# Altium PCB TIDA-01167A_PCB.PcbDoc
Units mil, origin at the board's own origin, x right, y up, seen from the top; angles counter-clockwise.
Board outline 1968.5 x 1574.8 mil, 2 copper layers (Top Layer, Bottom Layer), stack 62 mil thick; 65 components, 25 nets, 160 pads, 86 vias.
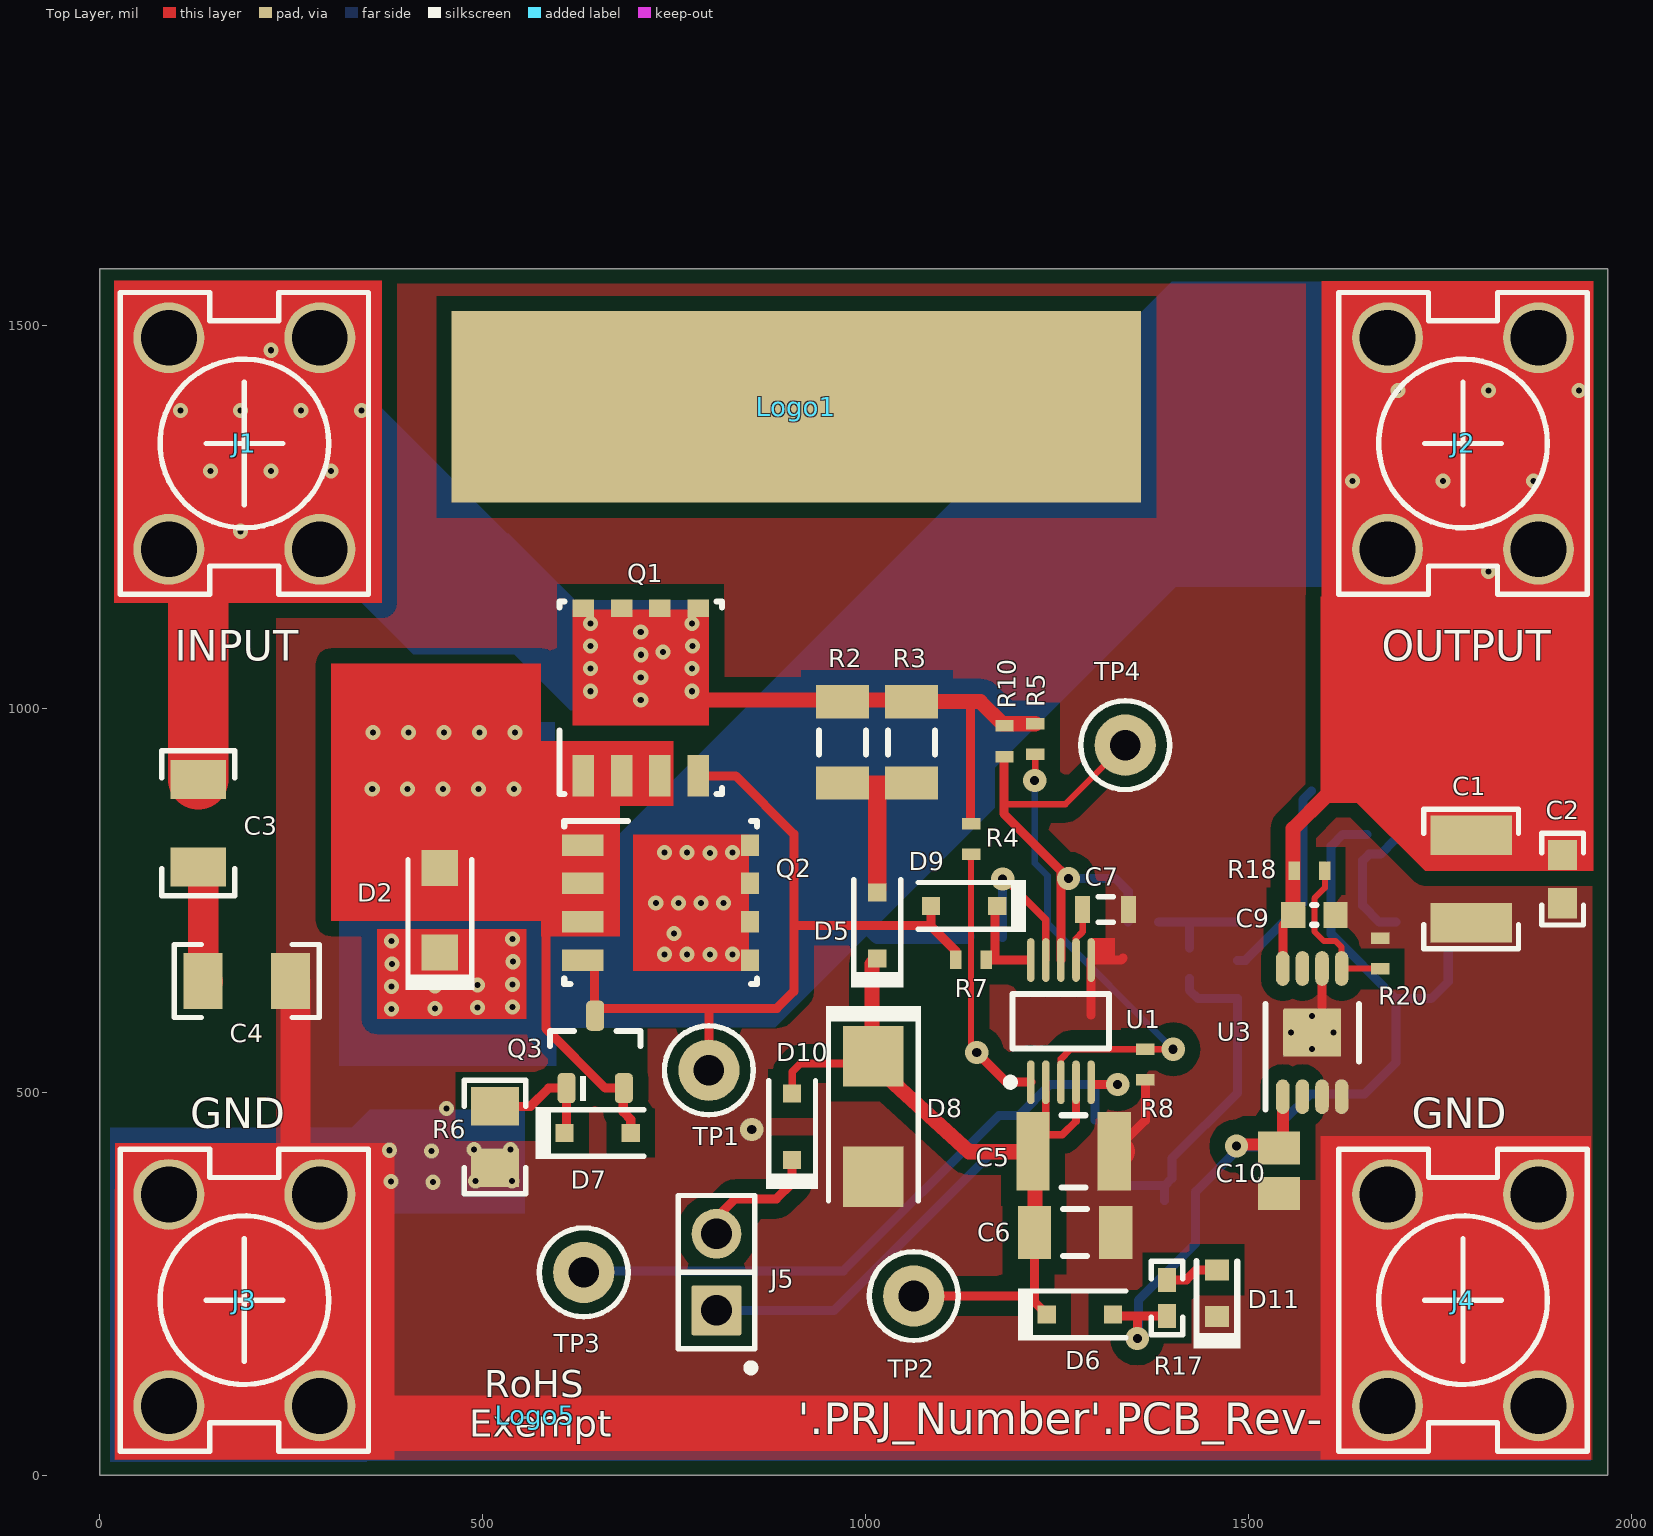
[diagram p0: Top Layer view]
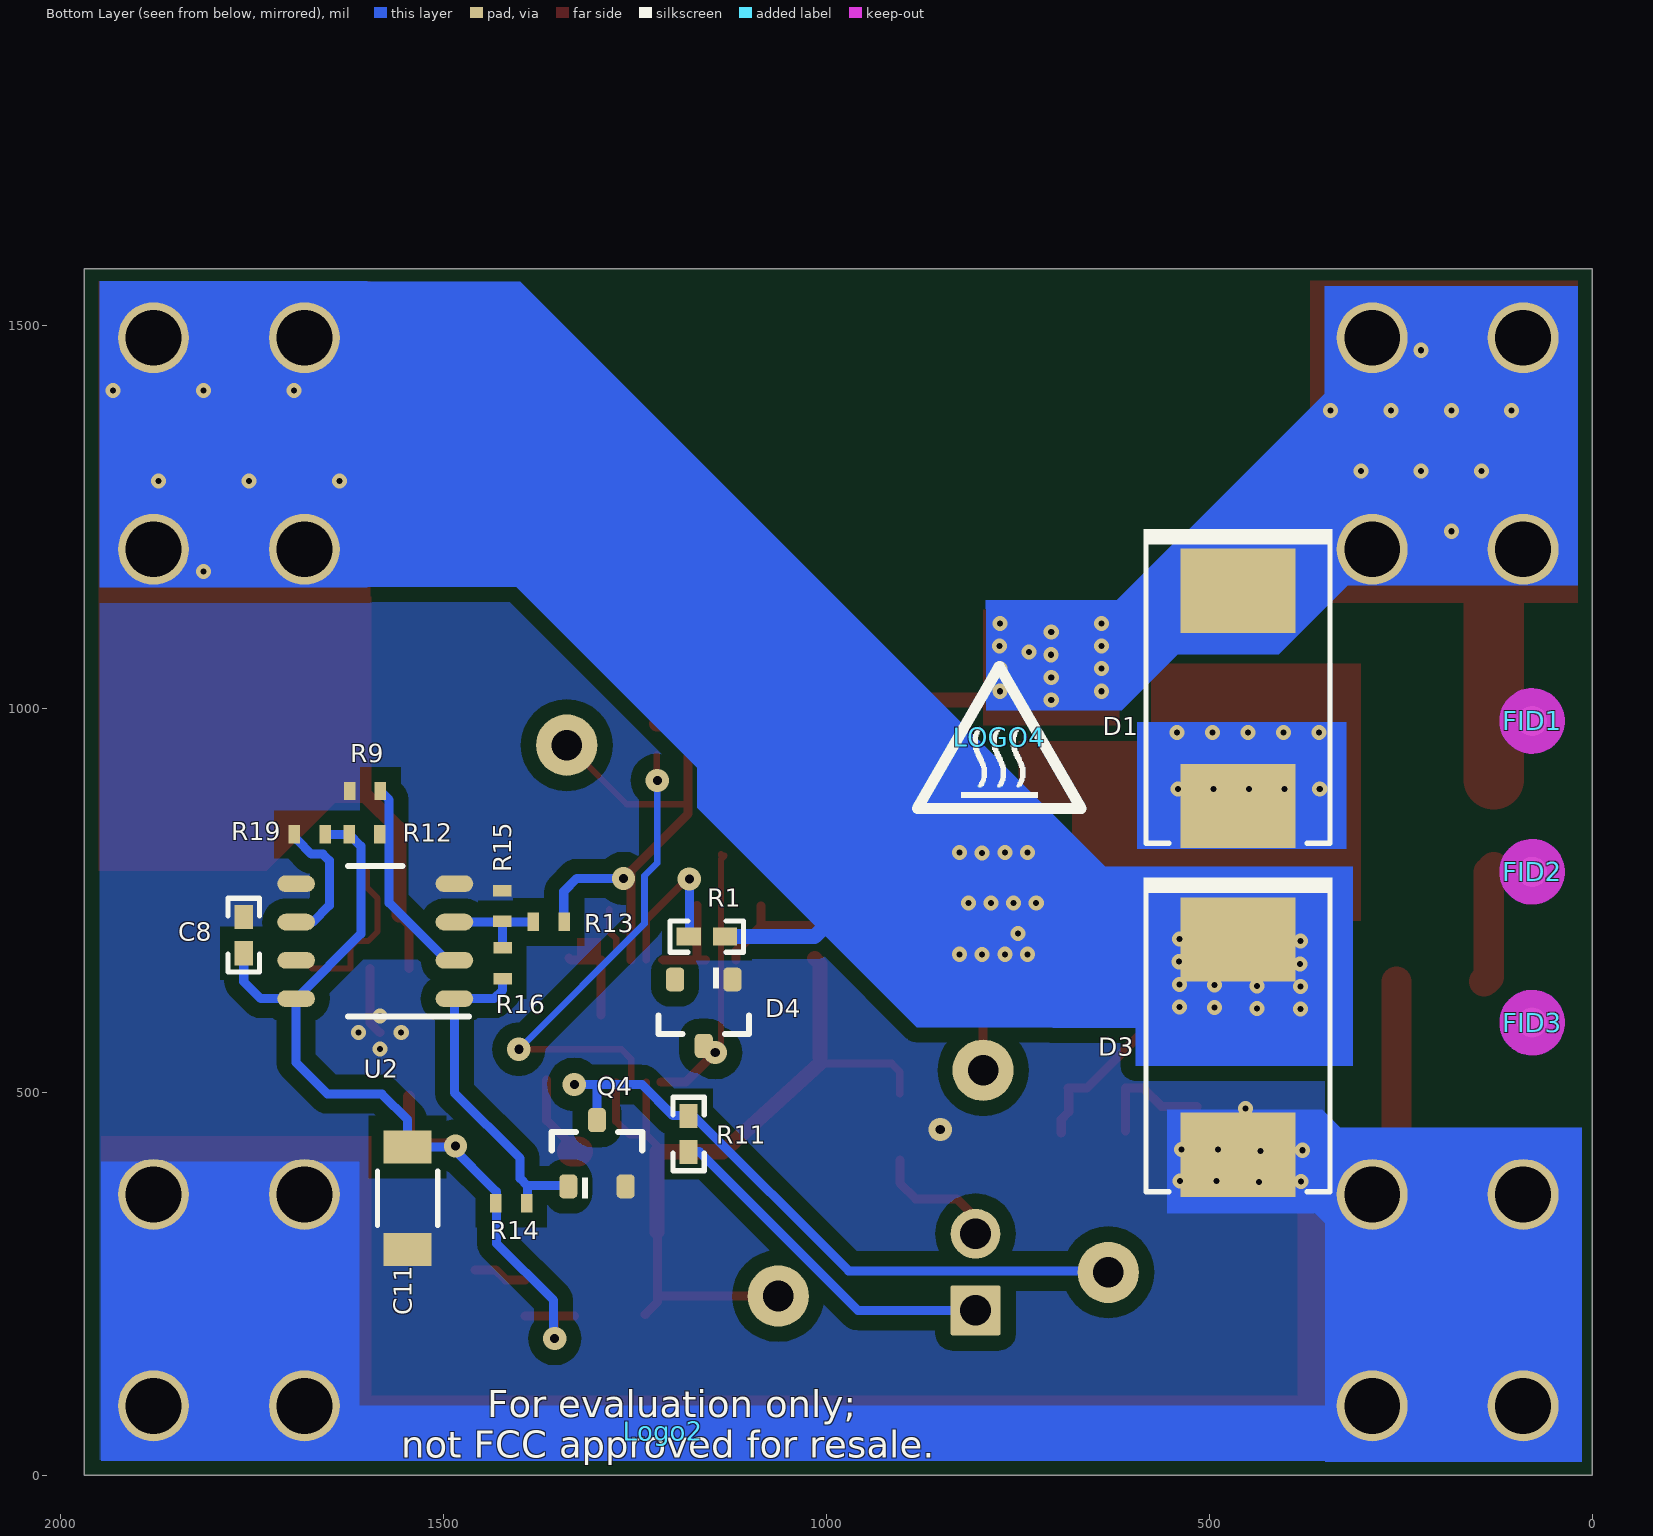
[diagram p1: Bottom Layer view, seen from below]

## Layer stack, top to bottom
Top Solder: solder mask 0.4, Solder Resist, Dk 3.5
Top Layer: signal copper 1.4
Dielectric1: core 59.2, FR-4, Dk 4.8
Bottom Layer: signal copper 1.4
Bottom Solder: solder mask 0.4, Solder Resist, Dk 3.5

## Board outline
0,0 1968.5,0 1968.5,1574.8 0,1574.8

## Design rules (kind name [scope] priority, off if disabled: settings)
AcuteAngle [All] p1: minimum=4.50000000000000E+0001 checktracksonly=FALSE
AssemblyTestPointUsage [All] p1: valid=2
BoardOutlineClearance BoardOutlineClearance_MountingHoles [OnCopper and InComponentClass('Mounting Holes')] p1: gap=19.68
BoardOutlineClearance BoardOutlineClearance_Poly [OnCopper and InPoly] p2: gap=19.68
BoardOutlineClearance [OnCopper and Not InComponentClass('Logo') and not InComponentClass('FiducialMark') and not InRegion(1000,500,4000,800)] p3: gap=0 except(19.68: Poly-OutlineEdge)
Clearance Clearance_1 [InNamedPolygon('BOTTOM_LAYER_GND_P000')] p1: gap=10
Clearance Clearance_Keepouts [((IsTrack Or IsArc) And Not InPoly) And IsFree and IsKeepOut vs ((IsTrack Or IsArc) And Not InPoly) And IsFree and IsKeepOut] p2: gap=15.75
Clearance Clearance_Poly [InPolygon] p3: gap=19.68
Clearance [All] p4: gap=7.87
ComponentClearance ComponentClearance_MountingHoles_FiducialMarks [InComponentClass('Mounting Holes') vs InComponentClass('FiducialMark')] p1: gap=50 collisioncheckmode=3 verticalgap=10 showdistances=FALSE
ComponentClearance ComponentClearance_Shunt [InComponentClass('Header') vs InComponentClass('Shunt')] p2: gap=0 collisioncheckmode=3 verticalgap=0 showdistances=FALSE
ComponentClearance ComponentClearance_Logo [InComponentClass('Logo')] p3: gap=50 collisioncheckmode=3 verticalgap=10 showdistances=FALSE
ComponentClearance ComponentClearance_ScrewToNut [(HasFootprint('NY PMS 440 0025 PH')) vs (HasFootprint('Keystone_1902C'))] p4: gap=5 collisioncheckmode=3 verticalgap=10 showdistances=FALSE
ComponentClearance ComponentClearance_MountingHoles [InComponentClass('Mounting Holes')] p5: gap=250 collisioncheckmode=3 verticalgap=100000 showdistances=FALSE
ComponentClearance ComponentClearance_SmallPassives [HasFootprint('0201*') or HasFootprint('0402*') or HasFootprint('0508') or HasFootprint('0603*') or HasFootprint('0612') or HasFootprint('0805*') or HasFootprint('0815*') or HasFootprint('0830*') or HasFootprint('1206*') or HasFootprint('1210*') or HasFootprint('1808*') or HasFootprint('1812*') or HasFootprint('1825*') or HasFootprint('2010*') or HasFootprint('2220*') or HasFootprint('2225*') or HasFootprint('2512*') or HasFootprint('2728*') or HasFootprint('3518*') vs HasFootprint('0201*') or HasFootprint('0402*') or HasFootprint('0508') or HasFootprint('0603*') or HasFootprint('0612') or HasFootprint('0805*') or HasFootprint('0815*') or HasFootprint('0830*') or HasFootprint('1206*') or HasFootprint('1210*') or HasFootprint('1808*') or HasFootprint('1812*') or HasFootprint('1825*') or HasFootprint('2010*') or HasFootprint('2220*') or HasFootprint('2225*') or HasFootprint('2512*') or HasFootprint('2728*') or HasFootprint('3518*')] p6: gap=14.96 collisioncheckmode=3 verticalgap=10 showdistances=FALSE
ComponentClearance ComponentClearance_THtoSMT [IsThruComponent vs IsSMTComponent] p7: gap=40 collisioncheckmode=3 verticalgap=30 showdistances=FALSE
ComponentClearance ComponentClearance_THtoTH [IsThruComponent vs IsThruComponent] p8: gap=30 collisioncheckmode=3 verticalgap=30 showdistances=FALSE
ComponentClearance [All] p9: gap=30 collisioncheckmode=3 verticalgap=3.94 showdistances=FALSE
DiffPairsRouting [All] p1: maxlimit=100 minlimit=10 mostfreqgap=10 toplayer_minwidth=15 toplayer_maxwidth=15 toplayer_prefwidth=15 bottomlayer_minwidth=15 bottomlayer_maxwidth=15 bottomlayer_prefwidth=15 maxuncoupledlength=1000
FabricationTestPointUsage TestPointUsage [All] p1: valid=2 allowmultiple=FALSE
FabricationTestpoint Testpoint [All] p1: side=3 testpointundercomponent=TRUE minsize=40 maxsize=100 preferedsize=60 minholesize=0 maxholesize=40 preferedholesize=32 testpointgrid=1 allowsidetop=TRUE allowsidebottom=TRUE usegrid=TRUE gridtolerance=0.01
FanoutControl Fanout_LCC [IsLCC] p1: bgadir=Out bgaviamode=Centered fanoutstyle=Auto fanoutdirection=Alternating viagrid=1 // Fanout_LCC (Default Rule)
FanoutControl Fanout_BGA [IsBGA] p2: bgadir=Out bgaviamode=Centered fanoutstyle=Auto fanoutdirection=Alternating viagrid=1 // Fanout_BGA (Default Rule)
FanoutControl Fanout_Default [All] p4: bgadir=Out bgaviamode=Centered fanoutstyle=Auto fanoutdirection=Alternating viagrid=1 // Fanout_Default (Default Rule)
FanoutControl Fanout_Small [(CompPinCount < 5)] p5: bgadir=Out bgaviamode=Centered fanoutstyle=Auto fanoutdirection=OutThenIn viagrid=1 // Fanout_Small (Default Rule)
HoleSize [All] p1: absolutevalues=TRUE maxlimit=251 minlimit=7.87 maxpercent=80.000 minpercent=20.000
MinimumAnnularRing MinimumAnnularRing_ThermalPadVias [IsVia and InAnyComponent] p1: minimumring=3.94
MinimumAnnularRing [All] p2: minimumring=5
MinimumSolderMaskSliver MinimumSolderMaskSliver_Logo [InComponentClass('Logo') vs InComponentClass('Logo')] p1: minsoldermaskwidth=0.7
MinimumSolderMaskSliver [All] p2: minsoldermaskwidth=4
PlaneConnect [All] p1: planeconnectstyle=Direct reliefexpansion=10 reliefentries=4 reliefconductorwidth=10 reliefairgap=10
PolygonConnect [All] p1: connectstyle=Direct reliefconductorwidth=10 reliefentries=4 polygonreliefangle="90 Angle" airgapwidth=10
RoutingVias ThermalPadVias [IsVia and InAnyComponent] p1: holewidth=7.87 width=19.68 viastyle="Through Hole" minholewidth=7.87 minwidth=19.68 maxholewidth=12.99 maxwidth=23.62
RoutingVias [All] p2: holewidth=16 width=34 viastyle="Through Hole" minholewidth=7.87 minwidth=19.68 maxholewidth=40 maxwidth=65
SilkToBoardRegionClearance [Not ((IsComment or IsDesignator) And (Hide <> 'False')) and not InRegion(1000,500,4000,800)] p1:
SilkToSilkClearance SilkToSilkClearance_Pb-FreeLogo [(HasFootprint('Pb-Free_Overlay_Medium') OR HasFootprint('Pb-Free_Overlay_Small')) vs (HasFootprint('Pb-Free_Overlay_Medium') OR HasFootprint('Pb-Free_Overlay_Small'))] p1: silktosilkclearance=0
SilkToSilkClearance [All] p2: silktosilkclearance=0
SilkToSolderMaskClearance SilkToComponentPadClearance [IsPad and InAnycomponent] p1: minsilkscreentomaskgap=0 clearancetoexposedcopper=TRUE
SilkToSolderMaskClearance "Silk to Solder Mask Opening" [All] p2: minsilkscreentomaskgap=0 clearancetoexposedcopper=FALSE
SolderMaskExpansion [All] p1: expansion=1.18
Width [All] p1: maxlimit=100 minlimit=6 preferedwidth=10 checkconnectedcopper=TRUE
15 further rules are at their usual default settings.

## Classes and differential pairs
component class TIDA-01167A_AutomotiveInputProtection: C1 C2 C3 C4 C5 C6 C7 C8 C9 C10 C11 D1 D2 D3 D4 D5 D6 D7 D8 D9 D10 D11 J1 J2 J3 J4 J5 Q1 Q2 Q3 Q4 R1 R2 R3 R4 R5 R6 R7 R8 R9 R10 R11 R12 R13 R14 R15 R16 R17 R18 R19 R20 TP1 TP2 TP3 TP4 U1 U2 U3
component class Header: J5
component class FiducialMark: FID1 FID2 FID3
component class TIDA-01167A_Hardware: FID1 FID2 FID3 Logo1 Logo2 LOGO4 Logo5
component class Logo: Logo1

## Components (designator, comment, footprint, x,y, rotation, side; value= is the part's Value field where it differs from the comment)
C1 "GRM32ER71K475KE14L" 1210_270 1790.16,777.95 r270 top
C2 "GRM188R72A104KA35J" 0603 1909.45,777.95 r270 top
C3 "VJ1206Y104KBBAT4X" 1206 128.74,850.79 r270 top
C4 "VJ1206Y104KBBAT4X" 1206 192.13,644.88 r180 top
C5 "GRM32ER71K475KE14L" 1210_270L 1271.26,422.44 r0 top
C6 "VJ1206Y104KBBAT4X" 1206L 1273.23,316.54 r0 top
C7 "GRM188R71H104KA93D" 0603S 1312.99,738.19 r0 top
C8 "GRM155R71E104KE14D" 0402 1760.24,704.72 r270 bottom
C9 "GRM188R72A104KA35J" 0603L 1585.43,731.1 r0 top
C10 "GRM219R61E106MA12" 0805L 1539.37,397.24 r270 top
C11 "GRM31CR61A476KE15L" 1206_180 1546.46,361.42 r270 bottom
D1 "5.0SMDJ24A" SMC 462.6,1013.78 r270 bottom
D2 "PTVS13VS1UR,115" SOD-123W 444.09,737.4 r90 top
D3 "5.0SMDJ54A" SMC 462.6,558.66 r270 bottom
D4 "BZX84C68LT1G" SOT-23L 1159.84,603.54 r270 bottom
D5 "BAS316,115" sod-323 1014.96,717.32 r90 top
D6 "1N5711WS-7-F" sod-323 1279.53,209.84 r0 top
D7 "1N4448WX-TP" sod-323 650,446.46 r0 top
D8 "SMAJ60A" SMA 1009.84,468.11 r270 top
D9 "BAS 170W E6327" SOD-323 1128.35,742.91 r180 top
D10 "1N5711WS-7-F" sod-323 903.94,454.72 r90 top
D11 "LNJ337W83RA" LNJx37x8_Green 1458.27,237.4 r90 top
FID1 "Fiducial" Fiducial10-20 78.74,984.25 r180 bottom
FID2 "Fiducial" Fiducial10-20 78.74,787.4 r180 bottom
FID3 "Fiducial" Fiducial10-20 78.74,590.55 r180 bottom
J1 "7693" 7693 188.98,1346.46 r0 top
J2 "7693" 7693 1779.53,1346.46 r0 top
J3 "7693" 7693 188.98,228.35 r0 top
J4 "7693" 7693 1779.53,228.35 r0 top
J5 "HTSW-102-07-G-S" Samtec_HTSW-102-07-G-S 805.12,264.96 r90 top
Logo1 "Texas Instruments" TI_Stacked_SolderMask_Small 909.45,1394.09 r0 top
Logo2 "FCC disclaimer" FCC_disclaimer_stacked 1212.6,57.09 r180 bottom
LOGO4 "CAUTION HOT SURFACE" IEC_HotSurface_Small 774.02,962.99 r180 bottom
Logo5 "EU RoHS Exempt Logo" EURoHS_Exempt_60mil_Stacked 568.9,77.95 r0 top
Q1 "CSD19532Q5B" TRANS_NexFET_Q5B 706.3,1022.05 r90 top
Q2 "CSD19532Q5B" TRANS_NexFET_Q5B 739.76,747.24 r0 top
Q3 "MMBTA06-7-F" SOT-23 646.85,552.36 r90 top
Q4 "BSS169H6327XTSA1" SOT-23L 1299.21,420.08 r90 bottom
R1 "CRCW040210K0FKED" 0402 1155.91,702.76 r0 bottom
R2 "CRCW1206200RFKEA" 1206L 969.69,956.3 r90 top
R3 "CRCW1206200RFKEA" 1206L 1059.69,956.3 r90 top
R4 "CRCW040210K0FKED" 0402S 1137.8,830.32 r270 top
R5 "CRCW0402510KJNED" 0402S 1221.26,960.63 r90 top
R6 "CRCW0805392KFKEA" 0805_HV 516.14,441.34 r90 top
R7 "CRCW04022K00FKED" 0402S 1137.4,672.44 r180 top
R8 "CRCW040215K0JNED" 0402S 1364.96,535.83 r90 top
R9 "CRCW040210K0FKED" 0402S 1601.97,892.91 r0 bottom
R10 "CRCW0402261KFKED" 0402S 1181.1,957.87 r90 top
R11 "CRCW040210K0FKED" 0402 1179.53,445.28 r270 bottom
R12 "CRCW040210K0FKED" 0402S 1602.76,836.22 r180 bottom
R13 "CRCW0402261KFKED" 0402S 1362.2,722.05 r0 bottom
R14 "CRCW040210K0FKED" 0402S 1411.02,354.72 r0 bottom
R15 "CRCW040218K0FKED" 0402S 1422.83,742.91 r270 bottom
R16 "CRCW040210K0FKED" 0402S 1422.44,668.11 r270 bottom
R17 "CRCW040210K0FKED" 0402 1393.31,231.1 r90 top
R18 "CRCW0402261KFKED" 0402S 1579.13,788.58 r180 top
R19 "CRCW040210K0FKED" 0402S 1674.02,836.22 r0 bottom
R20 "CRCW0402510KJNED" 0402S 1671.65,680.71 r270 top
TP1 "5000" Keystone5000 795.28,528.35 r0 top
TP2 "5000" Keystone5000 1062.73,233.71 r0 top
TP3 "5004" Keystone5004 631.89,264.57 r0 top
TP4 "5004" Keystone5004 1338.58,952.76 r0 top
U1 "LM5060Q1MMX/NOPB" MUB10A_L 1254.72,592.52 r90 top
U2 "LM2903AVQD" D0008A_L 1588.58,696.85 r0 bottom
U3 "TPS7A1650DGNR" DGN0008C_L 1582.68,577.56 r90 top

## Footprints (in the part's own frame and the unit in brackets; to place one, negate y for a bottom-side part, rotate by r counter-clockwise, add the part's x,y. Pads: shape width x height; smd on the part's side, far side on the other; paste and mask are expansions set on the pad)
0402 [mm] "0402 from SM-752 data"
  rect 0.8x0.6 smd: 1(-0.6,0) 2(0.6,0)
  silkscreen extent -1.22,-0.52 1.22,0.52, body extent -0.55,-0.3 0.55,0.3, height 0.6
0402S [mil] "Based on C0402S footprint from PADS legacy"
  rect 15x24 smd: 1(-20,0) 2(20,0)
  body extent -22,-12 22,12, height 24
0603 [mm] "0603 from SM-752 data"
  rect 1x0.95 smd: 1(-0.8,0) 2(0.8,0)
  silkscreen extent -1.52,-0.69 1.52,0.69, body extent -0.87,-0.47 0.87,0.47, height 1
0603L [mm] "0603 from SM-752 data"
  rect 0.8x0.85 smd: 1(-0.7,0) 2(0.7,0)
  silkscreen extent -0.07,-0.33 0.07,0.33, body extent -0.87,-0.47 0.87,0.47, height 1
0603S [mil]
  rect 20x35 smd: 1(-30,0) 2(30,0)
  silkscreen extent -10,-17 10,17, body extent -34,-19 34,19, height 39
0805_HV [mil] "0805 with 30mil clearance between pads"
  rect 50x63 smd: 1(-40,0) 2(40,0)
  silkscreen extent -74,-40 74,40, body extent -43,-29 43,29, height 57
0805L [mm] "0805 from SM-752 data"
  rect 1.1x1.4 smd: 1(-0.75,0) 2(0.75,0)
  body extent -1.1,-0.72 1.1,0.72, height 1.45
1206 [mm] "1206 from SM-752 data"
  rect 1.3x1.85 smd: 1(-1.45,0) 2(1.45,0)
  silkscreen extent -2.4,-1.21 2.4,1.21, body extent -1.7,-0.9 1.7,0.9, height 1.35
1206_180 [mm] "1206_180"
  rect 1.1x1.6 smd: 1(-1.7,0) 2(1.7,0)
  silkscreen extent -0.9,-1 0.9,1, body extent -1.75,-0.95 1.75,0.95, height 1.8
1206L [mm] "1206 from SM-752 data"
  rect 1.1x1.75 smd: 1(-1.35,0) 2(1.35,0)
  silkscreen extent -0.4,-0.77 0.4,0.77, body extent -1.7,-0.9 1.7,0.9, height 1.35
1210_270 [mm] "1210"
  rect 1.3x2.7 smd: 1(-1.45,0) 2(1.45,0)
  silkscreen extent -2.32,-1.57 2.32,1.57, body extent -1.7,-1.35 1.7,1.35, height 2.7
1210_270L [mm] "1210"
  rect 1.1x2.6 smd: 1(-1.35,0) 2(1.35,0)
  silkscreen extent -0.4,-1.2 0.4,1.2, body extent -1.7,-1.35 1.7,1.35, height 2.7
7693 [mm] "Keystone Electronics 7693 recommended land pattern"
  round 2.35 hole 1.85: 1(-2.502,3.505) 2(2.502,3.505) 3(-2.502,-3.505) 4(2.502,-3.505)
  silkscreen extent -4.11,-5 4.11,5, body extent -3.95,-3.94 3.95,3.96, height 8.86
D0008A_L [mm] "SOIC, 8-Leads, Body 4.9x3.9mm, Pitch 1.27mm, IPC High Density"
  oval 1.25x0.55 smd: 1(-2.625,1.905) 2(-2.625,0.635) 3(-2.625,-0.635) 4(-2.625,-1.905) 5(2.625,-1.905) 6(2.625,-0.635) 7(2.625,0.635) 8(2.625,1.905)
  silkscreen extent -3.1,-2.5 0.9,2.5, body extent -3,-2.45 3,2.45, height 1.63
DGN0008C_L [mm] "TSOP, 8-Leads, Body 3x3mm, Pitch 0.65mm, Thermal Pad 1.98x1.88mm, IPC High Density"
  rrect100% 1.15x0.45 smd: 1(-2.125,0.975) 2(-2.125,0.325) 3(-2.125,-0.325) 4(-2.125,-0.975) 5(2.125,-0.975) 6(2.125,-0.325) 7(2.125,0.325) 8(2.125,0.975)
  rrect6% 1.6x1.92 smd: 9(0,0)
  silkscreen extent -2.55,-1.55 0.95,1.55, body extent -2.46,-1.5 2.46,1.5, height 1.1
EURoHS_Exempt_60mil_Stacked [mil] "EU RoHS Exempt symbol"
FCC_disclaimer_stacked [mil]
Fiducial10-20 [mm]
  round 1 smd mask+0.5: 1(0,0)
  Top Layer keep-out circle w1.178: c0,0 r0.5
IEC_HotSurface_Small [mil]
  silkscreen extent -107,-93 107,92
Keystone5000 [mil] "For Keystone 500x miniature loop terminals"
  round 80 hole 40: 1(0,0)
  silkscreen extent -58,-58 58,58, body extent -49,-49 49,49, height 182
Keystone5004 [mil] "For Keystone 500x miniature loop terminals"
  round 80 hole 40: 1(0,0)
  silkscreen extent -58,-58 58,58, body extent -49,-49 49,49, height 182
LNJx37x8_Green [mm] "SMD, 2-Leads, Body 1.6x0.8mm"
  rect 0.7x0.8 smd: 1(0.775,0) 2(-0.775,0)
  silkscreen extent -1.82,-0.77 1.07,0.77, body extent -0.85,-0.45 0.85,0.45, height 0.25
MUB10A_L [mm] "TSSOP, 10-Leads, Body 3x3mm, Pitch 0.5mm, IPC High Density"
  oval 1.45x0.25 smd: 1(-2.025,1) 2(-2.025,0.5) 3(-2.025,0) 4(-2.025,-0.5) 5(-2.025,-1) 6(2.025,-1) 7(2.025,-0.5) 8(2.025,0) 9(2.025,0.5) 10(2.025,1)
  silkscreen extent -2.15,-1.6 0.9,1.8, body extent -1.6,-1.6 1.6,1.6, height 1.09
Samtec_HTSW-102-07-G-S [mm] "Samtec 100mil, 1x2, 230 mil above insulator"
  rrect6% 1.65x1.65 hole 1.016: 1(-1.27,0)
  round 1.65 hole 1.016: 2(1.27,0)
  silkscreen extent -3.3,-1.27 2.54,1.27, body extent -2.54,-1.27 2.54,1.27, height 8.38
SMA [mm] "Molded Diode, 2-Leads, Body 4.3x2.6mm, IPC Medium Density, based on OnSemi component dimensions and land pattern"
  rect 2x2 smd: 1(-2,0) 2(2,0)
  silkscreen extent -3.66,-1.57 2.79,1.57, body extent -2.6,-1.3 2.6,1.3, height 2.42
SMC [mil] "Molded Diode, 2-Leads, Body 6.9x5.8mm, IPC Medium Density, based on OnSemi component dimensions and land patterns"
  rect 110x150 smd: 1(-140.49,0) 2(140.49,0)
  silkscreen extent -221,-124 189,123, body extent -156,-116 156,116, height 91
SOD-123W [mm] "NXP recommended land pattern"
  rect 1.2x1.2 smd paste-0.05: 1(-1.4,0) 2(1.4,0)
  silkscreen extent -2.64,-1.14 1.68,1.14, body extent -1.85,-0.95 1.85,0.95, height 1.1
sod-323 [mm] "NXP recommended land pattern"
  rect 0.6x0.6 smd paste-0.05: 1(-1.1,0) 2(1.1,0)
  silkscreen extent -2.06,-0.86 1.53,0.86, body extent -1.3,-0.67 1.3,0.68, height 1.1
SOD-323 [mm] "NXP recommended land pattern"
  rect 0.6x0.6 smd paste-0.05: 1(-1.1,0) 2(1.1,0)
  silkscreen extent -2.06,-0.86 1.53,0.86, body extent -1.3,-0.67 1.3,0.68, height 1.1
SOT-23 [mm] "SOT23, 3-Leads, Body 2.9x1.3mm, Pitch 0.95mm, Lead Span 2.5mm, IPC Medium Density"
  rrect50% 1x0.6 smd: 1(-1.2,0.95) 2(-1.2,-0.95) 3(1.2,0)
  silkscreen extent -1.62,-1.5 0.7,1.5, body extent -1.16,-1.45 1.21,1.45, height 1
SOT-23L [mm] "SOT23, 3-Leads, Body 2.9x1.3mm, Pitch 0.95mm, Lead Span 2.5mm, IPC High Density"
  rrect50% 0.8x0.6 smd: 1(-1.1,0.95) 2(-1.1,-0.95) 3(1.1,0)
  silkscreen extent -1.5,-1.5 0.7,1.5, body extent -1.16,-1.45 1.21,1.45, height 1
TI_Stacked_SolderMask_Small [mil]
  rect 900x250 smd paste-125 mask-125: 0(0,0)
TRANS_NexFET_Q5B [mm] "TI recommended land pattern (nominal) November 2012"
  rect 1.372x0.71 smd paste-0.4: 1(-2.776,1.905) 2(-2.776,0.635) 3(-2.776,-0.635) 4(-2.776,-1.905)
  rect 0.59x0.71 smd paste-0.3: 5(2.776,-1.905) 6(2.776,-0.635) 7(2.776,0.635) 8(2.776,1.905)
  Top Layer region: -1.106,-2.26 2.744,-2.26 2.744,2.26 -1.106,2.26
  silkscreen extent -3.38,-2.7 3,2.7, body extent -3.23,-2.55 2.87,2.55, height 1.06

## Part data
C1 C5: "CAP, CERM, 4.7 µF, 80 V, +/- 10%, X7R, 1210"
C2 C9: "CAP, CERM, 0.1 µF, 100 V, +/- 10%, X7R, 0603"
C3 C4 C6: "CAP, CERM, 0.1 µF, 100 V, +/- 10%, X7R, 1206"
C7: "CAP, CERM, 0.1 µF, 50 V, +/- 10%, X7R, 0603"
C8: "CAP, CERM, 0.1 µF, 25 V, +/- 10%, X7R, 0402"
C10: "CAP, CERM, 10 µF, 25 V, +/- 20%, X5R, 0805"
C11: "CAP, CERM, 47 µF, 10 V, +/- 10%, X5R, 1206"
D1: "Diode, TVS, Uni, 24 V, 5000 W, SMC"
D2: "Diode, TVS, Uni, 13 V,  W, SOD-123W"
D3: "Diode, TVS, Uni, 54 V, 5000 W, SMC"
D4: "Diode, Zener, 68 V, 225 mW, SOT-23"
D5: "Diode, Ultrafast, 100 V, 0.25 A, SOD-323"
D6 D10: "Diode, Schottky, 70 V, 0.015 A, SOD-323"
D7: "Diode, Switching, 75 V, 0.25 A, SOD-323"
D8: "Diode, TVS, Uni, 60 V, 400 W, SMA"
D9: "Diode, Schottky, 70 V, 0.07 A, AEC-Q101, SOD-323"
D11: "LED, Green, SMD"
FID1 FID2 FID3: "Fiducial mark.  There is nothing to buy or mount."
J1 J2 J3 J4: "Terminal screw, vertical, snap-in"
J5: "Header, 100mil, 2x1, Gold, TH"
Logo1: library part TI_Logo, "Texas Instrument Corporate Signature"
Logo2: library part FCC_disclaimer, "FCC_disclaimer"
LOGO4: library part IEC_HotSurface, "IEC 61010-1 Hot Surface Warning"
Logo5: library part EURoHS_Exempt
Q1 Q2: "MOSFET, N-CH, 100 V, 17 A, SON 5x6mm"
Q3: library part "MMBTA06-7-F, Diodes Inc.", "Transistor, NPN, 80 V, 0.5 A, SOT-23"
Q4: "MOSFET, N-CH, 100 V, 0.17 A, SOT-23"
R1 R4 R9 R11 R12 R14 R16 R17 R19: "RES, 10.0 k, 1%, 0.063 W, 0402"
R2 R3: "RES, 200, 1%, 0.25 W, 1206"
R5 R20: "RES, 510 k, 5%, 0.063 W, 0402"
R6: "RES, 392 k, 1%, 0.125 W, 0805"
R7: "RES, 2.00 k, 1%, 0.063 W, 0402"
R8: "RES, 15 k, 5%, 0.063 W, 0402"
R10 R13 R18: "RES, 261 k, 1%, 0.063 W, 0402"
R15: "RES, 18.0 k, 1%, 0.063 W, AEC-Q200 Grade 0, 0402"
TP1 TP2: "Test Point, Miniature, Red, TH"
TP3 TP4: "Test Point, Miniature, Yellow, TH"
U1: "High-Side Protection Controller with Low Quiescent Current, 10-pin MSOP, Pb-Free"
U2: "Dual Comparator, D0008A"
U3: "Single Output LDO, 100 mA, Fixed 5 V Output, 3 to 60 V Input, with Enable and Power Good, 8-pin MSOP (DGN), -40 to 125 degC, Green (RoHS & no Sb/Br)"

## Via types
v1: diameter 19.68, hole 7.87, Top Layer to Bottom Layer, 77 vias
v2: diameter 30.32, hole 11.81, Top Layer to Bottom Layer, 9 vias

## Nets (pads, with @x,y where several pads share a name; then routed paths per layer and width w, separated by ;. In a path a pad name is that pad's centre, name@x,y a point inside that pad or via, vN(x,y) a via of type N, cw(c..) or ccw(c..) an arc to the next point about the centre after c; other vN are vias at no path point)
DISABLE: Q4.1 R14.1 R16.2 U2.1 | length 437.4
  Bottom Layer w11.81: Q4.1@1337.8,377.95 1390.16,377.95 ; R14.1@1390.16,358.66 1390.16,377.95 ; R16.2 1422.44,633.07 1433.66,621.85 U2.1 1485.24,499.02 1399.61,413.39 1399.61,387.4 1390.16,377.95
GND: C1.2 C2.2 C4.1 C5.2 C6.2 C7.2 C8.1 C9.2 C10.2 C11.2 D3.2 D4.1 D8.2 D11.2 J3.1 J3.2 J3.3 J3.4 J4.1 J4.2 J4.3 J4.4 Q4.2 R6.1 R8.1 R9.2 R15.1 R20.1 U1.6 U2.4 U2.5 U3.3 U3.4 U3.6 U3.9 | length 618.8
  Top Layer w11.81: 1294.09,600.39 U1.6 1333.27,672.24 1335.83,674.8 ; C5.2 1364.96,462.99 R8.1 ; U3.9 1595.47,590.35 U3.6
  Top Layer w39.37: C4.1@255.51,644.09 255.51,374.69 J3.2@275.67,354.54 ; C5.2 C5.2@1331.5,422.44
  other v1: 435.04,382.28 380.32,383.07 490.55,383.86 538.19,383.86 433.07,423.23 378.35,424.02 488.58,424.8 536.22,424.8 452.76,478.35 1582.68,555.91 1554.72,577.56 1610.63,577.56 1582.68,599.21
  other v2: 851.18,451.18
INPUT_KL30: C3.1 D1.1 J1.1 J1.2 J1.3 J1.4 Q1.5 Q1.6 Q1.7 Q1.8 R2.2 R3.2 R4.1 R5.2 R10.2 | length 878.2
  Top Layer w11.81: R4.1@1136.61,850.32 1136.61,1009.45
  Top Layer w19.68: 766.93,1011.42 R3.2@1057.72,1011.42 ; R3.2 1136.61,1009.45 1149.53,1009.45 1178.35,980.63 R5.2
  Top Layer w78.74: C3.1 128.74,1157.84 132.17,1161.27
  other v1: 706.34,1011.6 640.59,1023.07 773.42,1023.07 706.34,1041.16 640.59,1052.63 773.42,1052.63 706.73,1070.71 735.32,1074.43 640.98,1082.18 773.82,1082.18 706.34,1100.26 640.59,1111.73 773.42,1111.73 184.14,1231.91 144.77,1310.65 223.51,1310.65 302.25,1310.65 105.4,1389.39 184.14,1389.39 262.88,1389.39 341.62,1389.39 223.51,1468.13
NetC3_2: C3.2 C4.2 | length 154.8
  Top Layer w39.37: C3.2 135.43,787.01 135.43,650 C4.2@141.34,644.09
NetC7_1: C7.1 U1.7 | length 54.1
  Top Layer w8.66: U1.7@1274.02,687.8 1274.02,700.01 1282.99,708.98 C7.1
NetD4_3: D4.3 R4.2 U1.1 | length 355
  Top Layer w7.87: R4.2@1137.11,810.32 1137.11,808.46 1132.53,808.46 1137.11,803.89 1137.11,559.35 v2(1144.88,551.57)
  Top Layer w11.81: v2(1144.88,551.57) 1183.66,512.8 U1.1
NetD5_2: D5.2 R2.1 R3.1 | length 224.3
  Top Layer w19.68: R2.1 R3.1
  Top Layer w23.62: D5.2@1014.96,764.96 1014.96,899.21
NetD7_1: D7.1 Q3.1 R6.2 | length 159.1
  Top Layer w11.81: R6.2 562.44,481.34 586.22,505.12 Q3.1 D7.1@609.45,449.21
NetD9_1: D9.1 R7.1 U1.10 | length 126.5
  Top Layer w7.87: U1.10@1212.6,672.24 U1.10
  Top Layer w11.81: R7.1@1157.8,672.44 1157.99,672.24 U1.10@1212.6,672.24 ; 1168.9,674.8 D9.1@1168.9,743.7
NetD9_2: D9.2 Q1.4 Q2.4 Q3.3 R7.2 TP1.1 | length 1034.5
  Top Layer w11.81: Q2.4@646.06,668.9 646.06,609.15 798.43,609.15 ; Q1.4 830.17,912.74 906.3,836.61 906.3,717.32 ; TP1.1 795.28,606 798.43,609.15 ; 1085.04,718.11 D9.2 ; R7.2@1117.8,672.44 1117.8,683.78 1084.25,717.32 906.3,717.32 ; 798.43,609.15 883.95,609.15 906.3,631.5 906.3,717.32
NetD10_1: D10.1 J5.2 | length 177.8
  Top Layer w11.81: J5.2@783.86,314.96 829.53,360.63 883.46,360.63 903.94,381.1 D10.1
NetD11_1: D11.1 R17.2 | length 70.4
  Top Layer w11.81: R17.2 1418.5,254.72 1431.69,267.91 D11.1
NetJ5_1: J5.1 R11.2 | length 481.4
  Bottom Layer w11.81: J5.1@783.86,214.96 958.66,214.96 1165.75,422.05 R11.2@1179.53,422.05
NetQ4_3: Q4.3 R11.1 TP3.1 U1.5 | length 871.1
  Top Layer w11.81: U1.5@1297.05,509.84 v2(1328.74,509.84)
  Bottom Layer w11.81: TP3.1@633.86,266.54 970.87,266.54 1173.62,469.29 1200,469.29 1240.55,509.84 v2(1328.74,509.84) ; Q4.3 1299.21,507.09
NetR1_2: R1.2 U1.9 | length 207.9
  Top Layer w9.84: v2(1178.74,777.95) 1180.32,779.53 1234.84,725 U1.9@1234.84,672.44
  Bottom Layer w11.81: R1.2@1178.74,701.97 v2(1178.74,777.95)
NetR5_1: R5.1 R8.2 U1.3 | length 644.2
  Top Layer w8.66: v2@1221.26,904.33 R5.1 ; U1.3 1254.72,543.31 1267.24,555.83 R8.2 v2(1401.18,555.83)
  Bottom Layer w8.66: v2(1220.47,906.69) 1220.47,798.93 1237.2,782.2 1237.2,719.81 v2(1401.18,555.83)
NetR9_1: R9.1 R12.2 U2.2 | length 267.1
  Bottom Layer w11.81: U2.2 1495.47,671.85 1570.47,746.85 1570.47,881.42 R9.1
NetR13_2: R13.2 R15.2 R16.1 U2.3 | length 136.6
  Bottom Layer w11.81: R13.2@1382.4,721.85 R15.2@1422.44,721.85 ; R16.1 R15.2@1422.44,721.85 ; U2.3 R15.2@1422.44,721.85
NetR18_1: R18.1 R20.2 U3.5 | length 206.9
  Top Layer w7.87: R18.1 1599.13,766.43 1585.43,752.73 1585.43,709.48 1598.06,696.85 1613.39,696.85 1621.06,689.17 U3.5 R20.2@1671.14,661.22
NetR19_2: R19.2 U2.6 | length 164.1
  Bottom Layer w11.81: R19.2@1690.55,829.13 1671.86,810.44 1656.9,810.44 1648.57,802.11 1648.57,743.61 1670.33,721.85 U2.6
PGD: R10.1 R13.1 TP4.1 U1.8 | length 620.5
  Top Layer w7.87: 1180.32,875.59 1260.63,875.59 1338.19,953.15 TP4.1
  Top Layer w11.81: R10.1@1180.32,938.19 1180.32,875.59 1180.32,863.39 1254.72,788.98 U1.8 ; v2@1264.56,770.86 v2(1264.56,778.74) v2@1264.56,779.14
  Bottom Layer w11.81: v2(1264.56,778.74) 1325.58,778.74 1342.6,761.72 1342.6,722.44 R13.1
V_BATT: C1.1 C2.1 C9.1 D2.1 D3.1 J2.1 J2.2 J2.3 J2.4 Q2.5 Q2.6 Q2.7 Q2.8 R1.1 R18.2 U3.8 | length 438.7
  Top Layer w11.81: U3.8 1544.29,717.52 C9.1
  Top Layer w19.68: C9.1 1557.87,843.7 1600,885.83
  Bottom Layer w19.68: 962.99,755.12 1015.35,702.76 R1.1
  other v1: 381.1,608.22 437.76,608.74 493.27,610.32 538.98,610.97 381.1,637.74 437.76,638.27 493.27,639.84 538.98,640.5 381.5,667.3 539.37,670.05 796.51,679.37 737.4,679.76 766.95,679.76 826.06,679.76 381.1,696.85 538.98,699.61 749.61,707.09 785.04,746.46 725.93,746.85 755.49,746.85 814.59,746.85 796.51,812.2 737.4,812.6 766.95,812.6 826.06,812.6 1812.6,1179.53 1635.43,1297.64 1753.54,1297.64 1871.65,1297.64 1694.49,1415.75 1812.6,1415.75 1930.71,1415.75
V_INTERNAL: D1.2 D2.2 D7.2 Q1.1 Q1.2 Q1.3 Q2.1 Q2.2 Q2.3 Q3.2 | length 334
  Top Layer w11.81: 589.76,722.44 582.68,715.35 582.68,582.68 660.24,505.12 Q3.2 ; Q3.2@683.46,500 683.46,474 693.31,464.16 D7.2
  other v1: 355.91,895.67 402.17,895.67 448.43,895.67 494.68,895.67 540.94,895.67 357.09,969.29 403.35,969.29 449.61,969.29 495.87,969.29 542.13,969.29
VCC_5V: C8.2 C10.1 C11.1 D6.2 R12.1 R14.2 R17.1 R19.1 U2.8 U3.1 | length 1265.1
  Top Layer w11.81: D6.2@1328.74,207.48 R17.1 ; v2(1354.38,178.3) 1354.38,206.64
  Top Layer w15.75: v2@1492.32,431.69 1544.29,431.69 U3.1
  Bottom Layer w11.81: v2@1355.91,178.3 1355.91,227.95 1430.48,302.53 1430.48,369.85 1491.73,431.1 1494.49,428.35 C11.1 1546.46,463.78 1579.92,497.24 1650.79,497.24 1691.93,538.39 U2.8 ; R12.1 1607.48,820.94 1607.48,706.3 U2.8 ; R12.1@1626.38,836.22 R19.1 ; C8.2 1760.24,644.09 1737.99,621.85 U2.8
  other v2: 1483.86,429.53
VIN_LM5060: C5.1 C6.1 D5.1 D6.1 D8.1 D10.2 TP2.1 U1.2 U1.4 | length 1097.8
  Top Layer w9.84: D10.2 903.94,526.44 914.7,537.2 1008.27,537.2 D8.1@1008.27,545.28 ; C5.1@1218.11,427.17 C5.1@1235.04,444.09 ; U1.2 C5.1@1235.04,444.09 ; U1.4 1274.41,461.81 1256.69,444.09 C5.1@1235.04,444.09
  Top Layer w11.81: TP2.1 1218.11,233.71 ; C6.1 1220.08,225.98 D6.1
  Top Layer w19.68: D8.1@1008.27,537.2 1134.65,422.05 1220.87,422.05 C6.1@1220.87,317.32 ; D8.1@1008.27,545.28 1008.27,667.32 D5.1
pads on no net: D4.2 FID1.1 FID2.1 FID3.1 Logo1.0 U2.7 U3.2 U3.7

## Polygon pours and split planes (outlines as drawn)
GND on Top Layer "TOP_LAYER_GND_P002" (solid, remove dead copper, pour order 2): 5.51,1571.26 7.48,1569.29 1967.72,1569.29 1967.72,7.48 1965.75,5.51 1956.3,14.96 3.54,14.96
GND on Bottom Layer "BOTTOM_LAYER_GND_P004" (solid, remove dead copper, pour order 4): 1978.74,1167.32 1175.59,1167.32 1173.23,1169.68 870.47,866.93 870.47,847.24 710.63,847.24 537.01,673.62 451.57,588.19 322.05,588.19 322.05,404.33 317.32,399.61 314.96,397.24 16.93,397.24 16.93,24.41 37.01,4.33 38.19,5.51 1960.24,5.51 1960.24,1164.96 1968.9,1173.62

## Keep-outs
Keep-Out Layer:
  text ".Layer_Name" at 577,-858.49 h60

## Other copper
Top Layer:
  rectangle net V_INTERNAL: 575.98,702.76 679.13,734.06
  rectangle net V_INTERNAL: 575.98,707.68 678.74,722.83
  rectangle net V_INTERNAL: 302.36,723.23 622.44,903.15
  rectangle net V_INTERNAL: 302.76,873.62 748.82,958.27
  rectangle net V_INTERNAL: 302.36,846.46 576.42,1059.06
  rectangle net V_INTERNAL: 302.36,886.91 553.33,1054.72
  rectangle net GND: 20.07,20.07 384.64,433.46
  rectangle net GND: 1593.7,20.08 1946.85,442.91
  rectangle net V_BATT: 1594.49,1137.4 1949.61,1558.27
  rectangle net INPUT_KL30: 18.9,1138.19 368.5,1559.06
  rectangle net V_BATT: 362.2,595.28 557.09,712.6
  rectangle net GND: 352.96,31.35 1617.53,104.18
  rectangle net GND: 1293.7,674.8 1325.59,700.79
  region net V_INTERNAL: 678.74,911.22 678.74,707.68 607.87,707.68 590.16,725.39 311.81,725.39 305.91,731.3 306.69,732.09 306.69,913.58 305.12,915.16
  pour cut-out: 714.57,584.65 715.09,584.12 715.09,525.58 657.1,525.58 640.94,541.73 640.94,568.9 651.57,568.9 668.9,586.22
  region net V_BATT: 1593.7,1146.65 1948.82,1146.65 1949.61,1147.44 1949.61,788.78 1729.92,788.78 1640.94,877.76 1598.82,877.76 1593.7,877.76
  pour cut-out: -17.72,1160.24 235.04,1160.24 230.71,1155.91 230.71,373.23 -2.36,373.23 -20.08,390.94
  text ".Layer_Name" at 577,-858.49 h60
Bottom Layer:
  rectangle net V_BATT: 350.79,618.9 637.4,653.54
  rectangle net GND: 1609.06,18.11 1946.85,409.06
  rectangle net INPUT_KL30: 614.57,998.03 791.73,1139.37
  rectangle net V_INTERNAL: 320.87,817.32 594.09,983.07
  rectangle net V_BATT: 312.6,614.17 662.6,794.17
  rectangle net V_BATT: 1598.43,1158.27 1948.43,1558.27
  rectangle net GND: 28.82,17.32 348.82,437.32
  rectangle net INPUT_KL30: 19.29,1161.42 349.29,1551.42
  rectangle net GND: 336.61,18.11 1620.47,90.55
  rectangle net V_BATT: 620.08,602.36 704.72,643.7
  rectangle net GND: 13.78,17.32 340.55,453.54
  rectangle net V_BATT: 312.6,583.86 704.72,645.28
  rectangle net V_BATT: 312.6,534.25 596.46,583.86
  rectangle net INPUT_KL30: 781.5,1130.32 791.93,1142.32
  pour cut-out: 1590.55,729.13 1595.28,724.41 1595.28,696.06 1618.5,672.83 1522.05,672.83 1522.05,680.31 1571.65,729.92 1584.25,729.92
  pour cut-out: 348.43,1229.72 349.65,1228.5 349.65,394.49 7.28,394.49 7.09,394.68 7.09,1229.72
  region net GND: 555.91,477.17 555.12,476.38 555.12,341.73 363.39,341.73 362.6,342.52 298.03,277.95 124.02,277.95 130.32,284.25 130.32,435.04 310.63,435.04 352.76,477.17
  region net INPUT_KL30: 614.57,998.03 522.36,1090.24 394.17,1090.24 533.46,1229.53 620.87,1142.13 788.98,1142.13 790.16,1140.94
  region net INPUT_KL30: 409.29,1071.42 319.29,1161.42 19.29,1161.42 19.29,1551.42 349.29,1551.42 349.29,1411.42 569.29,1191.42 569.29,1071.42
  region net V_BATT: 1626.38,1166.14 1626.38,1557.48 1399.61,1557.48 698.82,856.69 698.82,584.65 881.89,584.65 883.86,586.61 883.86,688.98 934.25,688.98 1404.72,1159.45 1616.54,1159.45
  region net V_BATT: 881.89,584.65 1168.11,870.87 1168.11,971.65 1157.09,982.68 992.91,818.5 912.99,818.5 912.99,811.02 727.95,625.98 690.94,625.98
  region net V_BATT: 698.82,856.69 624.8,782.68 624.8,628.74 625.98,627.56 627.56,629.13 702.76,629.13
  text ".Layer_Name" at 577,-858.49 h60

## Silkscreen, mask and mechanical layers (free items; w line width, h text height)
Top Overlay:
  text "INPUT" at 98.43,1062.99 h39.37
  text "OUTPUT" at 1673.23,1062.99 h39.37
  text "INPUT" at -2535.43,937.8 h39.37
  text "GND" at 118.11,452.76 h39.37
  text "GND" at 1712.6,452.76 h39.37
  text "'.PRJ_Number'.PCB_Rev-" at 911.02,39.37 h70.87
  text ".Layer_Name" at 577,-858.49 h60
Bottom Overlay:
  text ".Layer_Name" at 577,-858.49 h60
Top Paste:
  text ".Layer_Name" at 577,-858.49 h60
Bottom Paste:
  text ".Layer_Name" at 577,-858.49 h60
Top Solder:
  text ".Layer_Name" at 577,-858.49 h60
  text ".Layer_Name" at 577,-858.49 h60
Bottom Solder:
  text ".Layer_Name" at 577,-858.49 h60
Drill Guide:
  text ".Layer_Name" at 577,-858.49 h60
M1 Board Outline:
  the board outline again, w10
  text ".Layer_Name" at 577,-858.49 h60
M2 Board Dimensions:
  rectangle: 125,-400 500,-275
  rectangle: 0,-275 125,-150
  lines w7: 0,-275 1000,-275 ; 125,-400 125,-150 ; 250,-400 250,-150 ; 500,-400 500,-150 ; 750,-400 750,-150 ; 0,-400 0,-150 1000,-150 1000,-400 0,-400
  text ".Layer_Name" at 577,-858.49 h60
M3 3D STEP Top:
  text ".Layer_Name" at 577,-858.49 h60
M4 3D STEP Bottom:
  text ".Layer_Name" at 577,-858.49 h60
M5 Assembly Top:
  lines w10: -292,-930.17 6308,-930.17 ; -292,-726.83 6310,-726.83 ; -292,-523.5 -292,-1133.5 3713,-1133.5 6310,-1133.5 6310,-523.5 -291.5,-523.5 -291.5,-1133.5 1284,-1133.5 ; 2173,-1133.5 2173,-523.5 ; 3440,-726.83 3440,-523.5 ; 4280,-726.83 4280,-523.5 ; 4902,-1140 4902,-937.17
  text "COMPONENTS MARKED 'DNP' SHOULD NOT BE POPULATED." at 1153.5,-318.5 h60
  text "ASSEMBLY VARIANT:" at 1153,-434 h60
  text ".VariantName" at 2189,-434 h60
  text "PCB VIEWED FROM TOP SIDE" at -228.5,-655.67 h60
  text "BOARD #:" at 2248,-655.67 h60
  text ".PRJ_Number" at 2793.5,-655.67 h60
  text "REV:" at 3638,-655.67 h60
  text ".PCB_Rev" at 3929.5,-655.67 h60
  text "SVN REV:" at 4476,-655.67 h60
  text ".VersionControl_RevNumber" at 4982,-655.67 h60
  text "TID #:" at 2248,-859 h60
  text ".TID" at 2793.5,-859 h60
  text "PLOT NAME =" at -228.5,-1064.34 h60
  text ".plot_File_Name" at 577,-1064.34 h60
  text "GENERATED    :" at 2250,-1064.34 h60
  text ".Print_Date" at 3119.5,-1064.34 h60
  text ".Print_Time" at 3848.5,-1064.34 h60
  text "TEXAS INSTRUMENTS" at 5113,-1064.34 h60
M6 Assembly Bottom:
  lines w10: -292.5,-727.33 6309.5,-727.33 ; -290.5,-930.67 6309.5,-930.67 ; 1115.5,-1140.5 1115.5,-937.67 ; 1737.5,-727.33 1737.5,-524 ; 2577.5,-727.33 2577.5,-524 ; 3844.5,-1134 3844.5,-524 ; 4733.5,-1134 6309,-1134 6309,-524 -292.5,-524 -292.5,-1134 2304.5,-1134 6309.5,-1134 6309.5,-524
  text "COMPONENTS MARKED 'DNP' SHOULD NOT BE POPULATED." at 6102,-318 h60
  text ".VariantName" at 5058,-434 h60
  text "ASSEMBLY VARIANT:" at 6097,-434 h60
  text ".VersionControl_RevNumber" at 1035.5,-656.17 h60
  text "SVN REV:" at 1541.5,-656.17 h60
  text ".PCB_Rev" at 2088,-656.17 h60
  text "REV:" at 2379.5,-656.17 h60
  text ".PRJ_Number" at 3224,-656.17 h60
  text "BOARD #:" at 3769.5,-656.17 h60
  text "PCB VIEWED FROM BOTTOM SIDE" at 6246,-656.17 h60
  text ".TID" at 3224,-859.5 h60
  text "TID #:" at 3769.5,-859.5 h60
  text "TEXAS INSTRUMENTS" at 904.5,-1064.84 h60
  text ".Print_Time" at 2169,-1064.84 h60
  text ".Print_Date" at 2898,-1064.84 h60
  text "GENERATED    :" at 3767.5,-1064.84 h60
  text ".plot_File_Name" at 5440.5,-1064.84 h60
  text "PLOT NAME =" at 6246,-1064.84 h60
M9 Title Sheet:
  drawing of 57 lines, arcs and shapes, not listed
  text "1" at 739.84,8036.5 h70
  text "2" at 3235.5,8036.5 h70
  text "3" at 5724.84,8036.5 h70
  text "4" at 8231.51,8036.5 h70
  text "5" at 10730.5,8036.5 h70
  text "6" at 13235.5,8036.5 h70
  text "A" at -416.5,6893.5 h70
  text "A" at 14383.5,6893.5 h70
  text "B" at -416.5,4513.5 h70
  text "B" at 14383.5,4513.5 h70
  text "C" at -416.5,2138.5 h70
  text "C" at 14383.5,2138.5 h70
  text "PROJECT TITLE:" at 11343.5,277.5 h45
  text ".PRJ_Title" at 11393.5,144.17 h70
  text "DESIGNED FOR:" at 11343.5,-23.5 h45
  text ".PRJ_Customer" at 11393.5,-163.5 h70
  text "D" at -416.5,-231.5 h70
  text "D" at 14383.5,-231.5 h70
  text "FILE NAME:" at 11343.5,-323.5 h45
  text ".PCB_File_Name_No_Path" at 11393.5,-443.5 h70
  text "Texas Instruments (TI) and/or its licensors do not warrant the accuracy or completeness of this specification" at 6374,-605.34 h45
  text "ENGINEER:" at 11343.5,-613.5 h45
  text "LAYOUT BY:" at 12848.5,-613.5 h45
  text "or any information contained therein. TI and/or its licensors do not warrant that this design will meet" at 6329.01,-718 h45
  text ".PRJ_Engineer" at 11393.5,-768.49 h70
  text ".PCB_Layout" at 12899,-768.49 h70
  text "the specifications, will be suitable for your application or fit for any particular purpose, or will operate in" at 6329.01,-830.67 h45
  text ".Layer_Name" at 577,-858.49 h60
  text "ALTIUM DESIGNER VERSION:" at 12848.5,-923.5 h45
  text "an implementation. TI and/or its licensors do not warrant that the design is production worthy. You should" at 6329.01,-943.33 h45
  text "completely validate and test your design implementation to confirm the system functionality for your application." at 6374,-1056 h45
  text ".print_Scale" at 11393.5,-1056.83 h70
  text ".Application_BuildNumber" at 12899,-1056.83 h70
  text "1" at 739.84,-1263.5 h70
  text "2" at 3235.5,-1263.5 h70
  text "3" at 5724.84,-1263.5 h70
  text "4" at 8231.51,-1263.5 h70
  text "5" at 10730.5,-1263.5 h70
  text "6" at 13235.5,-1263.5 h70
M10 Fab Notes:
  drawing of 173 lines, arcs and shapes, not listed
  text "DESIGN INFORMATION" at 12378.02,6201 h60
  text "MIN. TRACK WIDTH:" at 11733.46,6021 h60
  text "8" at 12829.7,6021 h60
  text "MIL" at 12984.46,6021 h60
  text "MIN. CLEARANCE:" at 11733.46,5889 h60
  text "0.2" at 12769.7,5889 h60
  text "mm" at 12984.46,5889 h60
  text "MIN. VIA PAD SIZE:" at 11733.46,5757 h60
  text "24" at 12799.71,5757 h60
  text "MIL" at 12984.46,5757 h60
  text "0.05mm (2MIL)" at 12428.46,5615.29 h60
  text "MINIMUM ANNULAR RING" at 11404.23,5611 h60
  text "EXTERNAL" at 13136.46,5611 h60
  text "PER" at 11604.23,5493 h60
  text "IPC-D-275 CLASS 2 LEVEL C" at 11824.23,5493 h60
  text "MIL, HOLES" at 13312.46,5380.71 h60
  text "+/-" at 12920,5380 h60
  text "+/-" at 13774,5380 h60
  text "REGISTRATION TOLERANCES:" at 11404.23,5375 h60
  text "METAL" at 12604,5375 h60
  text "5" at 13180.2,5375 h60
  text "3" at 14013.2,5375 h60
  text "MIL" at 14129.46,5375 h60
  text "+/-" at 13774,5262 h60
  text "HOLE SIZE TOLERANCE (UNLESS OTHERWISE SPECIFIED):" at 11404.23,5257 h60
  text "3" at 14013.2,5257 h60
  text "MIL" at 14129.46,5257 h60
  text "MATERIAL:" at 11329.46,5047.54 h60
  text "FR-4 High Tg" at 12315.9,4907.21 h60
  text "FR-408" at 11750.46,4898.64 h60
  text "OTHER" at 13238.46,4898.64 h60
  text "X" at 12161,4895 h60
  text "62 MIL (1.6mm) +/-10%" at 12070.56,4735.92 h60
  text "THICKNESS:" at 11404.23,4731.64 h60
  text "X" at 11942.4,4731.64 h60
  text "OTHER" at 13355.46,4731.64 h60
  text "TOLERANCE:" at 11404.23,4573.64 h60
  text "X" at 12243.53,4573.64 h60
  text "ANSI IPC-6012 TYPE 3 CLASS 2" at 12430.48,4573.64 h60
  text "OTHER +/-" at 12430.46,4417.64 h60
  text "BOW & TWIST:" at 11404.23,4260.64 h60
  text "X" at 12243.53,4260.64 h60
  text "ANSI IPC-6012 TYPE 3 CLASS 2" at 12430.48,4260.64 h60
  text "OTHER +/-" at 12430.46,4102.13 h60
  text "DRILLING:" at 11329.46,3963.64 h60
  text "REFERENCE:" at 11404.23,3846.64 h60
  text "X" at 12052.46,3846.64 h60
  text "AS SHOWN" at 12239.46,3846.64 h60
  text "X" at 12953.46,3846.64 h60
  text "NC_DRILL FILES" at 13090.46,3846.64 h60
  text "PTH COPPER THICKNESS:" at 11404.23,3688.64 h60
  text "X" at 12534.46,3688.64 h60
  text "20-30 um" at 12671.46,3688.64 h60
  text "OTHER" at 13388.46,3688.64 h60
  text "BOARD FINISH:" at 11329.46,3529.64 h60
  text "SILKSCREEN:" at 11484.68,3411.64 h60
  text "X" at 12433.46,3411.64 h60
  text "TOP" at 12559.46,3411.64 h60
  text "X" at 12943.46,3411.64 h60
  text "BOTTOM" at 13070.46,3411.64 h60
  text "SILKSCREEN COLOR:" at 11484.68,3244.64 h60
  text "X" at 12432.42,3244.64 h60
  text "WHITE" at 12559.46,3244.64 h60
  text "OTHER" at 13070.46,3244.64 h60
  text "X" at 12563.42,3085.44 h60
  text "GREEN" at 12690.46,3085.44 h60
  text "OTHER" at 13308.46,3085.44 h60
  text "SOLDER RESIST COLOR:" at 11484.68,3074.64 h60
  text "X" at 12563.42,2915.44 h60
  text "MATTE" at 12690.46,2915.44 h60
  text "SEMI-GLOSS" at 13308,2914.8 h60
  text "IMMERSION GOLD (ENIG)" at 12390.46,2726.92 h60
  text "ENEPIG" at 13728,2723.64 h60
  text "SURFACE FINISH:" at 11329.46,2722.64 h60
  text "X" at 12203.51,2722.64 h60
  text "IMM. TIN/SILVER OR EQUIV" at 11659,2565.64 h60
  text "OTHER" at 13090.46,2565.64 h60
  text "ARRAY/PANEL:" at 11329.46,2386.64 h60
  text "CUT AND TRIM PER M1 BOARD OUTLINE" at 12390.46,2382.35 h60
  text "N.C. ROUTE" at 12390.46,2230.64 h60
  text "X" at 13069.46,2230.64 h60
  text "V. SCORE" at 13256.46,2230.64 h60
  text "CERTIFICATION:" at 11329.46,2093.64 h60
  text "MATERIALS AND WORKMANSHIP FOR ALL PCBS" at 12054.46,2093.64 h60
  text "TO MEET OR EXCEED THE REQUIREMENTS OF:" at 12054.46,1995.64 h60
  text "X" at 11680.96,1859.13 h60
  text "ANSI IPC-A-600F CLASS ->" at 11819.96,1859.13 h60
  text "X" at 13459.02,1859.13 h60
  text "2" at 13577.96,1859.14 h60
  text "1" at 13262.96,1857.64 h60
  text "3" at 13931.96,1857.64 h60
  text "X" at 12495.02,1699.64 h60
  text "RoHS" at 12631.96,1699.64 h60
  text "OTHER" at 13276.36,1699.64 h60
  text "PER ORDER" at 13673.42,1699.64 h60
  text "ALL BOARDS MUST MEET OR EXCEED UL94-V0 REQUIREMENTS." at 11357,1534 h60
  text "PCB MUST BEAR THE UL94V-0 UL REGISTERED MATERIAL ID NUMBER" at 11357,1414 h60
  text "ADDITIONAL REQUIREMENTS:" at 11329.46,1240.64 h60
  text "MICROSECTION:" at 11404.23,1125.64 h60
  text "YES" at 12309.96,1125.64 h60
  text "REQUIRED" at 13171.46,969.49 h60
  text "BARE BOARD ELEC. TEST:" at 11404.23,966.64 h60
  text "NONE" at 12709.96,966.64 h60
  text "X" at 13044.46,966.64 h60
  text "PER ORDER" at 13763.46,966.64 h60
  text ".Layer_Name" at 577,-858.49 h60
M11 Gerber Information:
  lines w10: -292,-930.17 6308,-930.17 ; -292,-726.83 6310,-726.83 ; -292,-523.5 -292,-1133.5 3713,-1133.5 6310,-1133.5 6310,-523.5 -291.5,-523.5 -291.5,-1133.5 1284,-1133.5 ; 2173,-1133.5 2173,-523.5 ; 3440,-726.83 3440,-523.5 ; 4280,-726.83 4280,-523.5 ; 4902,-1140 4902,-937.17
  text "ALL ARTWORK VIEWED FROM TOP SIDE" at -228.5,-655.67 h60
  text "BOARD #:" at 2248,-655.67 h60
  text ".PRJ_Number" at 2793.5,-655.67 h60
  text "REV:" at 3638,-655.67 h60
  text ".PCB_Rev" at 3929.5,-655.67 h60
  text "SVN REV:" at 4476,-655.67 h60
  text ".VersionControl_RevNumber" at 4982,-655.67 h60
  text "LAYER NAME =" at -228.5,-858.49 h60
  text "TID #:" at 2248,-859 h60
  text ".TID" at 2793.5,-859 h60
  text "PLOT NAME =" at -228.5,-1064.34 h60
  text ".plot_File_Name" at 577,-1064.34 h60
  text "GENERATED    :" at 2250,-1064.34 h60
  text ".Print_Date" at 3119.5,-1064.34 h60
  text ".Print_Time" at 3848.5,-1064.34 h60
  text "TEXAS INSTRUMENTS" at 5113,-1064.34 h60
M12 Stackup:
  drawing of 191 lines, arcs and shapes, not listed
  text "Layer" at 9790.34,7830 h60
  text "Name" at 10200.26,7830 h60
  text "Material" at 11130,7830 h60
  text "Thickness" at 11989.77,7830 h60
  text "Constant" at 12639.6,7830 h60
  text "Board Layer Stack" at 13209.46,7830 h60
  text "1" at 9790.34,7710 h60
  text "Top Overlay" at 10200.26,7710 h60
  text "2" at 9790.34,7590 h60
  text "Top Solder" at 10200.26,7590 h60
  text "Solder Resist" at 11130,7590 h60
  text "0.40mil" at 11989.77,7590 h60
  text "3.5" at 12639.6,7590 h60
  text "3" at 9790.34,7470 h60
  text "Top Layer" at 10200.26,7470 h60
  text "Copper" at 11130,7470 h60
  text "1.40mil" at 11989.77,7470 h60
  text "4" at 9790.34,7350 h60
  text "Dielectric1" at 10200.26,7350 h60
  text "FR-4" at 11130,7350 h60
  text "59.20mil" at 11989.77,7350 h60
  text "4.8" at 12639.6,7350 h60
  text "5" at 9790.34,7230 h60
  text "Bottom Layer" at 10200.26,7230 h60
  text "Copper" at 11130,7230 h60
  text "1.40mil" at 11989.77,7230 h60
  text "6" at 9790.34,7110 h60
  text "Bottom Solder" at 10200.26,7110 h60
  text "Solder Resist" at 11130,7110 h60
  text "0.40mil" at 11989.77,7110 h60
  text "3.5" at 12639.6,7110 h60
  text "7" at 9790.34,6990 h60
  text "Bottom Overlay" at 10200.26,6990 h60
  text ".Layer_Name" at 577,-858.49 h60
M13 Component Bodies Top:
  text ".Layer_Name" at 577,-858.49 h60
M14 Component Bodies Bottom:
  text ".Layer_Name" at 577,-858.49 h60
M15 Courtyards Top:
  text ".Layer_Name" at 577,-858.49 h60
M16 Courtyards Bottom:
  text ".Layer_Name" at 577,-858.49 h60
Drill Drawing:
  text ".Layer_Name" at 577,-858.49 h60
M17 Embedded Cavity:
  text ".Layer_Name" at 577,-858.49 h60
M18 Embedded Assembly:
  text ".Layer_Name" at 577,-858.49 h60
M19 Embedded Keepout:
  text ".Layer_Name" at 577,-858.49 h60

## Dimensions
0,0 to 1968.5,0 on M2 Board Dimensions
0,0 to 0,1574.8 on M2 Board Dimensions
0,-400 to 1000,-400 on M2 Board Dimensions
